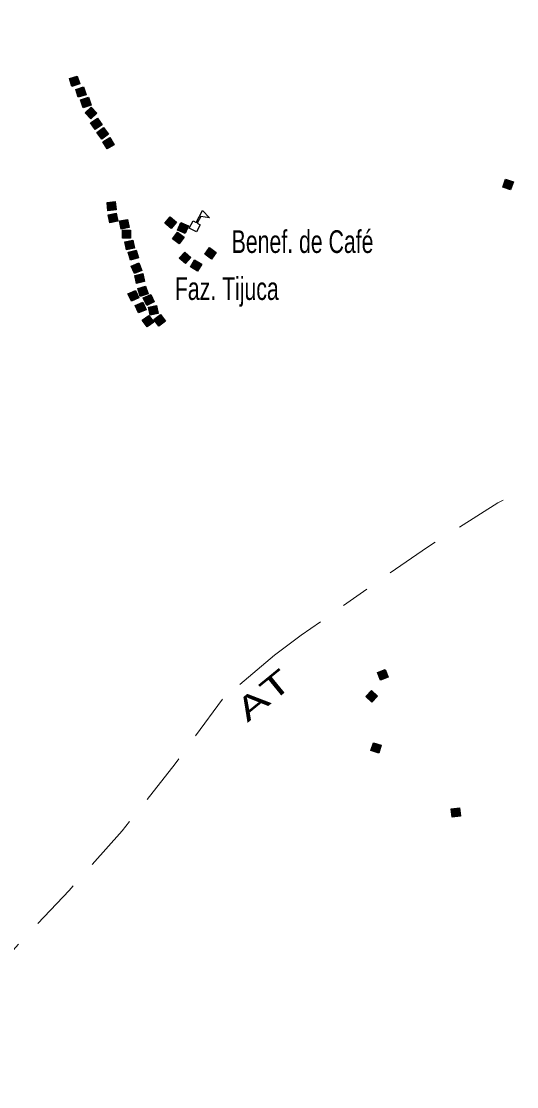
# Model space of a CAD drawing. Extents: x 679 to 705, y 7427.4 to 7455.4.
# Drawn here: x 692.837 to 694.583, y 7439.999 to 7443.755 of the extents above; entities that cross this region are included whole.
import ezdxf
from ezdxf.enums import TextEntityAlignment as Align

# ---------------------------------------------------------------- set-up
doc = ezdxf.new("R2010")
doc.units = 0
doc.header["$LTSCALE"] = 0.032
doc.linetypes.add('DOT_DASHED', pattern=[7.7, 5, -1.2, 0.3, -1.2])
for name, color, linetype, lineweight in [('2', 7, 'Continuous', 25), ('4', 7, 'Continuous', 25), ('56', 7, 'DOT_DASHED', 13)]:
    doc.layers.add(name, color=color, linetype=linetype, lineweight=lineweight)
doc.layers.add('61', color=7, linetype='Continuous')

msp = doc.modelspace()

# ---------------------------------------------------------------- hatches: boundary and pattern name
at = {"layer": '2'}
for points in [[(693.0339, 7443.5623), (693.0427, 7443.5347), (693.015, 7443.5259), (693.0063, 7443.5536)], [(693.056, 7443.5242), (693.0652, 7443.4966), (693.0376, 7443.4875), (693.0285, 7443.515)], [(693.0735, 7443.4875), (693.0827, 7443.4599), (693.0552, 7443.4508), (693.046, 7443.4783)], [(693.0832, 7443.4527), (693.1028, 7443.4313), (693.0814, 7443.4117), (693.0618, 7443.4331)], [(693.1053, 7443.4141), (693.1214, 7443.3899), (693.0973, 7443.3739), (693.0812, 7443.398)], [(693.1262, 7443.3808), (693.144, 7443.3579), (693.1212, 7443.3401), (693.1033, 7443.3629)], [(693.1494, 7443.3452), (693.1641, 7443.3203), (693.1392, 7443.3055), (693.1244, 7443.3305)], [(694.5435, 7443.1983), (694.5709, 7443.1889), (694.5614, 7443.1615), (694.534, 7443.1709)], [(693.1679, 7443.1198), (693.1711, 7443.0909), (693.1423, 7443.0877), (693.1391, 7443.1166)], [(693.1713, 7443.0793), (693.177, 7443.0508), (693.1486, 7443.0451), (693.1429, 7443.0736)], [(693.2114, 7443.0568), (693.2167, 7443.0283), (693.1882, 7443.0229), (693.1829, 7443.0514)], [(693.3614, 7443.0663), (693.3836, 7443.0476), (693.3648, 7443.0254), (693.3427, 7443.0442)], [(693.2221, 7443.0194), (693.2221, 7442.9904), (693.1931, 7442.9904), (693.1931, 7443.0194)], [(693.3874, 7443.0119), (693.4106, 7442.9945), (693.3932, 7442.9713), (693.37, 7442.9887)], [(693.3987, 7443.0457), (693.4255, 7443.0345), (693.4143, 7443.0078), (693.3876, 7443.0189)], [(693.2303, 7442.9835), (693.236, 7442.9551), (693.2076, 7442.9494), (693.2019, 7442.9778)], [(693.2421, 7442.949), (693.2495, 7442.921), (693.2214, 7442.9136), (693.214, 7442.9417)], [(693.4128, 7442.9419), (693.4346, 7442.9228), (693.4155, 7442.901), (693.3937, 7442.9201)], [(693.5004, 7442.9576), (693.5238, 7442.9405), (693.5066, 7442.9171), (693.4833, 7442.9343)], [(693.2507, 7442.904), (693.2621, 7442.8773), (693.2354, 7442.8659), (693.224, 7442.8926)], [(693.4476, 7442.9142), (693.4725, 7442.8993), (693.4576, 7442.8744), (693.4327, 7442.8893)], [(693.2649, 7442.8658), (693.2714, 7442.8375), (693.2432, 7442.831), (693.2367, 7442.8592)], [(693.2747, 7442.8219), (693.2835, 7442.7942), (693.2559, 7442.7854), (693.2471, 7442.8131)], [(693.2391, 7442.8068), (693.2511, 7442.7804), (693.2247, 7442.7684), (693.2127, 7442.7948)], [(693.2933, 7442.7924), (693.3053, 7442.766), (693.2789, 7442.754), (693.2669, 7442.7804)], [(693.2648, 7442.7652), (693.2765, 7442.7387), (693.25, 7442.727), (693.2383, 7442.7535)], [(693.2907, 7442.7196), (693.2849, 7442.748), (693.3132, 7442.7538), (693.3191, 7442.7254)], [(693.2864, 7442.7184), (693.3034, 7442.6949), (693.2799, 7442.6779), (693.2629, 7442.7014)], [(693.3278, 7442.7216), (693.3448, 7442.6981), (693.3214, 7442.6811), (693.3043, 7442.7045)], [(694.1193, 7441.4695), (694.1297, 7441.4425), (694.1027, 7441.432), (694.0922, 7441.459)], [(694.0709, 7441.396), (694.0921, 7441.3762), (694.0723, 7441.355), (694.0511, 7441.3748)], [(694.0776, 7441.2118), (694.1053, 7441.2032), (694.0967, 7441.1755), (694.069, 7441.1841)], [(694.3808, 7440.9821), (694.3844, 7440.9533), (694.3556, 7440.9497), (694.352, 7440.9785)]]:
    msp.add_hatch(color=256, dxfattribs=at).paths.add_polyline_path(points)

# ---------------------------------------------------------------- linework, layer by layer
for points in [[(693.0339, 7443.5623), (693.0427, 7443.5347), (693.015, 7443.5259), (693.0063, 7443.5536)], [(693.056, 7443.5242), (693.0652, 7443.4966), (693.0376, 7443.4875), (693.0285, 7443.515)], [(693.0735, 7443.4875), (693.0827, 7443.4599), (693.0552, 7443.4508), (693.046, 7443.4783)], [(693.0832, 7443.4527), (693.1028, 7443.4313), (693.0814, 7443.4117), (693.0618, 7443.4331)], [(693.1053, 7443.4141), (693.1214, 7443.3899), (693.0973, 7443.3739), (693.0812, 7443.398)], [(693.1262, 7443.3808), (693.144, 7443.3579), (693.1212, 7443.3401), (693.1033, 7443.3629)], [(693.1494, 7443.3452), (693.1641, 7443.3203), (693.1392, 7443.3055), (693.1244, 7443.3305)], [(694.5435, 7443.1983), (694.5709, 7443.1889), (694.5614, 7443.1615), (694.534, 7443.1709)], [(693.1679, 7443.1198), (693.1711, 7443.0909), (693.1423, 7443.0877), (693.1391, 7443.1166)], [(693.1713, 7443.0793), (693.177, 7443.0508), (693.1486, 7443.0451), (693.1429, 7443.0736)], [(693.2114, 7443.0568), (693.2167, 7443.0283), (693.1882, 7443.0229), (693.1829, 7443.0514)], [(693.3614, 7443.0663), (693.3836, 7443.0476), (693.3648, 7443.0254), (693.3427, 7443.0442)], [(693.2221, 7443.0194), (693.2221, 7442.9904), (693.1931, 7442.9904), (693.1931, 7443.0194)], [(693.3874, 7443.0119), (693.4106, 7442.9945), (693.3932, 7442.9713), (693.37, 7442.9887)], [(693.3987, 7443.0457), (693.4255, 7443.0345), (693.4143, 7443.0078), (693.3876, 7443.0189)], [(693.2303, 7442.9835), (693.236, 7442.9551), (693.2076, 7442.9494), (693.2019, 7442.9778)], [(693.2421, 7442.949), (693.2495, 7442.921), (693.2214, 7442.9136), (693.214, 7442.9417)], [(693.4128, 7442.9419), (693.4346, 7442.9228), (693.4155, 7442.901), (693.3937, 7442.9201)], [(693.5004, 7442.9576), (693.5238, 7442.9405), (693.5066, 7442.9171), (693.4833, 7442.9343)], [(693.2507, 7442.904), (693.2621, 7442.8773), (693.2354, 7442.8659), (693.224, 7442.8926)], [(693.4476, 7442.9142), (693.4725, 7442.8993), (693.4576, 7442.8744), (693.4327, 7442.8893)], [(693.2649, 7442.8658), (693.2714, 7442.8375), (693.2432, 7442.831), (693.2367, 7442.8592)], [(693.2747, 7442.8219), (693.2835, 7442.7942), (693.2559, 7442.7854), (693.2471, 7442.8131)], [(693.2391, 7442.8068), (693.2511, 7442.7804), (693.2247, 7442.7684), (693.2127, 7442.7948)], [(693.2933, 7442.7924), (693.3053, 7442.766), (693.2789, 7442.754), (693.2669, 7442.7804)], [(693.2648, 7442.7652), (693.2765, 7442.7387), (693.25, 7442.727), (693.2383, 7442.7535)], [(693.2907, 7442.7196), (693.2849, 7442.748), (693.3132, 7442.7538), (693.3191, 7442.7254)], [(693.2864, 7442.7184), (693.3034, 7442.6949), (693.2799, 7442.6779), (693.2629, 7442.7014)], [(693.3278, 7442.7216), (693.3448, 7442.6981), (693.3214, 7442.6811), (693.3043, 7442.7045)], [(694.1193, 7441.4695), (694.1297, 7441.4425), (694.1027, 7441.432), (694.0922, 7441.459)], [(694.0709, 7441.396), (694.0921, 7441.3762), (694.0723, 7441.355), (694.0511, 7441.3748)], [(694.0776, 7441.2118), (694.1053, 7441.2032), (694.0967, 7441.1755), (694.069, 7441.1841)], [(694.3808, 7440.9821), (694.3844, 7440.9533), (694.3556, 7440.9497), (694.352, 7440.9785)]]:
    msp.add_lwpolyline(points, close=True, dxfattribs=at)
at = {"layer": '4'}
for points in [[(693.4527, 7443.0461), (693.4754, 7443.0889), (693.4999, 7443.0627), (693.4693, 7443.0669), (693.4571, 7443.0438)], [(693.4571, 7443.0438), (693.4677, 7443.0382), (693.4541, 7443.0126), (693.4285, 7443.0262), (693.4421, 7443.0518), (693.4527, 7443.0461)]]:
    msp.add_lwpolyline(points, dxfattribs=at)
at = {"layer": '56'}
msp.add_lwpolyline([(697.8309, 7443.7554), (697.5731, 7443.6239), (697.3054, 7443.4844), (697.0473, 7443.3579), (696.7941, 7443.2281), (696.542, 7443.0961), (696.037, 7442.8424), (695.524, 7442.5825), (695.0163, 7442.3198), (694.7641, 7442.1893), (694.5164, 7442.0571), (694.2681, 7441.9019), (693.8232, 7441.5914), (693.7292, 7441.5206), (693.5456, 7441.3652), (693.3793, 7441.1375), (693.1926, 7440.9018), (693.0052, 7440.6906), (692.8076, 7440.4806), (692.6854, 7440.3538), (692.4502, 7440.1946), (692.1694, 7440.0116), (691.9405, 7439.8452)], dxfattribs=at)

# ---------------------------------------------------------------- texts
at = {"layer": '61', "width": 0.7}
for s, p in [('Benef. de Café', (693.5783, 7442.9387)), ('Faz. Tijuca', (693.3779, 7442.773))]:
    msp.add_text(s, height=0.08, dxfattribs=at).set_placement(p)
at = {"layer": '61', "width": 1.55}
msp.add_text('AT', height=0.08, rotation=39.225, dxfattribs=at).set_placement((693.7159, 7441.3485), align=Align.CENTER)

doc.saveas('drawing.dxf')
